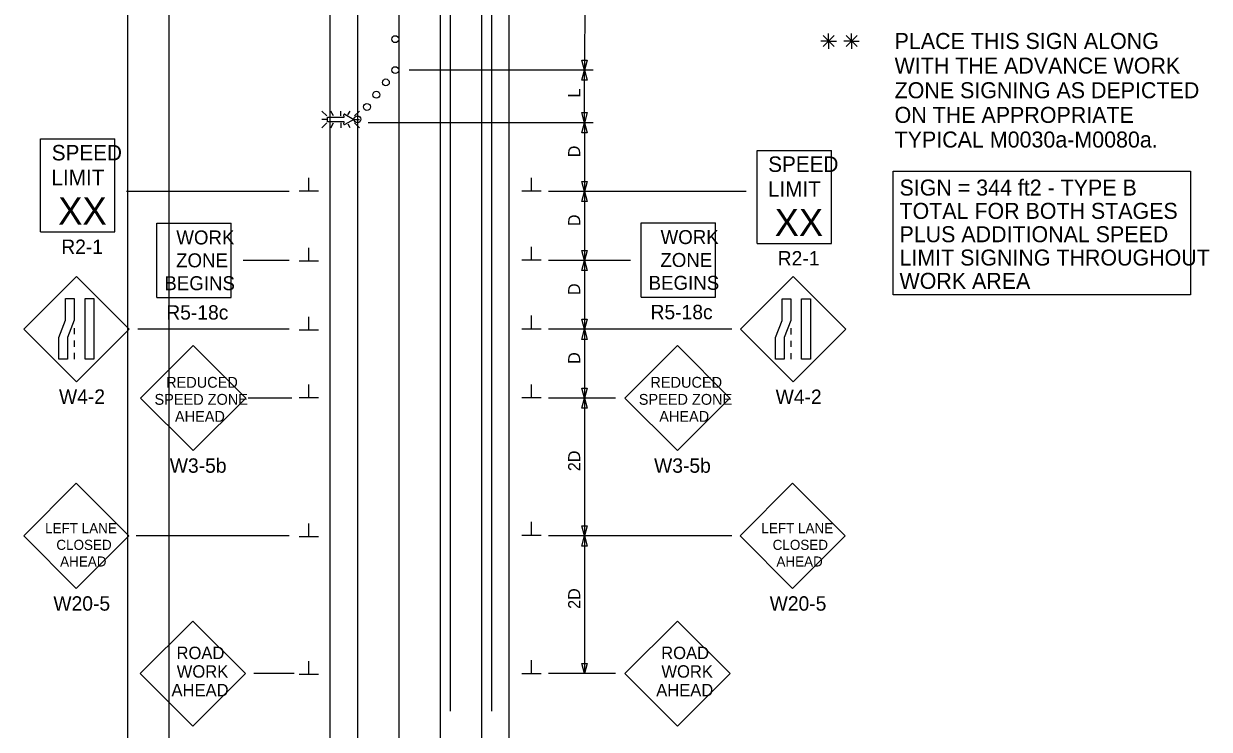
# Model space of a CAD drawing. Extents: x 16576 to 19504, y 5728 to 6974.
# Drawn here: x 16733 to 17422, y 6145 to 6555 of the extents above; entities that cross this region are included whole.
import ezdxf

# ---------------------------------------------------------------- set-up
doc = ezdxf.new("R2010")
doc.units = 0
for name, color, linetype in [('ALI_LEGAL_EX', 7, 'Continuous'), ('PAVT_EDGE_EX', 7, 'Continuous'), ('TRAFFIC_SIGNS_PR', 7, 'Continuous'), ('TYPICAL_TEXT_DIMEN_EX', 7, 'Continuous'), ('TYPICAL_TEXT_DIMEN_PR', 7, 'Continuous')]:
    doc.layers.add(name, color=color, linetype=linetype)

msp = doc.modelspace()

# ---------------------------------------------------------------- linework, layer by layer
at = {"layer": 'ALI_LEGAL_EX'}
for p, q in [((16980.68, 6974.12), (16980.68, 6155.98)), ((17004.68, 6974.12), (17004.68, 6155.98)), ((16950.77, 6911.88), (16950.77, 6082.69)), ((16974.77, 6911.88), (16974.77, 6082.69)), ((16793.2, 6891.57), (16793.2, 6027.66)), ((16817.2, 6891.57), (16817.2, 6027.66))]:
    msp.add_line(p, q, dxfattribs=at)
for points in [[(16950.77, 6511.88), (16950.77, 6486.88)], [(16974.77, 6511.88), (16974.77, 6486.88)], [(16950.77, 6411.88), (16950.77, 6386.88)], [(16974.77, 6411.88), (16974.77, 6386.88)], [(16950.77, 6311.88), (16950.77, 6286.88)], [(16974.77, 6311.88), (16974.77, 6286.88)], [(16950.77, 6211.88), (16950.77, 6186.88)], [(16974.77, 6211.88), (16974.77, 6186.88)]]:
    msp.add_lwpolyline(points, dxfattribs=at)
at = {"layer": 'PAVT_EDGE_EX'}
for p, q in [((16910.77, 6923.28), (16910.77, 5986.88)), ((16926.77, 6923.28), (16926.77, 5986.88)), ((16998.77, 6923.28), (16998.77, 5986.88)), ((17014.77, 6923.28), (17014.77, 5986.88))]:
    msp.add_line(p, q, dxfattribs=at)
at = {"layer": 'TRAFFIC_SIGNS_PR'}
for p, q in [((16908.93, 6501.61), (16906.11, 6504.43)), ((16908.93, 6499.58), (16906.11, 6499.58)), ((16912.88, 6501.61), (16911.26, 6504.43)), ((16917.02, 6501.61), (16917.02, 6504.43)), ((16921.2, 6502.25), (16922.46, 6504.43)), ((16927.92, 6504.43), (16925.1, 6501.61)), ((16925.1, 6499.58), (16927.92, 6499.58)), ((16908.93, 6497.55), (16906.11, 6494.73)), ((16911.23, 6494.73), (16912.86, 6497.55)), ((16917.02, 6497.55), (16917.02, 6494.73)), ((16922.49, 6494.73), (16921.28, 6496.82)), ((16927.92, 6494.73), (16925.1, 6497.55)), ((16742.6, 6488.3), (16785.8, 6488.3)), ((16742.6, 6434.3), (16742.6, 6488.3)), ((16785.8, 6434.3), (16785.8, 6488.3)), ((17159, 6481.61), (17202.2, 6481.61)), ((17159, 6427.61), (17159, 6481.61)), ((17202.2, 6427.61), (17202.2, 6481.61)), ((16810.23, 6396.18), (16810.23, 6439.38)), ((16810.23, 6439.38), (16853.43, 6439.38)), ((16853.43, 6396.18), (16853.43, 6439.38)), ((17091.69, 6396.39), (17091.69, 6439.59)), ((17091.69, 6439.59), (17134.89, 6439.59)), ((17134.89, 6396.39), (17134.89, 6439.59)), ((16742.6, 6434.3), (16785.8, 6434.3)), ((17159, 6427.61), (17202.2, 6427.61)), ((16763.47, 6408.35), (16732.92, 6377.81)), ((16794.02, 6377.81), (16763.47, 6408.35)), ((17179.99, 6408.26), (17149.44, 6377.72)), ((17210.53, 6377.72), (17179.99, 6408.26)), ((16810.23, 6396.18), (16853.43, 6396.18)), ((17091.69, 6396.39), (17134.89, 6396.39)), ((16732.92, 6377.81), (16763.47, 6347.26)), ((16762.07, 6378.36), (16762.07, 6374.76)), ((16763.47, 6347.26), (16794.02, 6377.81)), ((17149.44, 6377.72), (17179.99, 6347.17)), ((17178.58, 6378.27), (17178.58, 6374.67)), ((17179.99, 6347.17), (17210.53, 6377.72)), ((16762.07, 6371.16), (16762.07, 6367.56)), ((16831.25, 6368.32), (16800.71, 6337.77)), ((16861.8, 6337.77), (16831.25, 6368.32)), ((17112.72, 6368.32), (17082.17, 6337.77)), ((17143.26, 6337.77), (17112.72, 6368.32)), ((17178.58, 6371.07), (17178.58, 6367.47)), ((16762.07, 6363.96), (16762.07, 6360.36)), ((17178.58, 6363.87), (17178.58, 6360.27)), ((16800.71, 6337.77), (16831.25, 6307.22)), ((16831.25, 6307.22), (16861.8, 6337.77)), ((17082.17, 6337.77), (17112.72, 6307.22)), ((17112.72, 6307.22), (17143.26, 6337.77)), ((16763.33, 6288.22), (16732.79, 6257.68)), ((16793.88, 6257.68), (16763.33, 6288.22)), ((17179.64, 6288.22), (17149.09, 6257.68)), ((17210.19, 6257.68), (17179.64, 6288.22)), ((16732.79, 6257.68), (16763.33, 6227.13)), ((16763.33, 6227.13), (16793.88, 6257.68)), ((17149.09, 6257.68), (17179.64, 6227.13)), ((17179.64, 6227.13), (17210.19, 6257.68)), ((16831.1, 6208.22), (16800.56, 6177.68)), ((16861.65, 6177.68), (16831.1, 6208.22)), ((17112.8, 6208.22), (17082.25, 6177.68)), ((17143.34, 6177.68), (17112.8, 6208.22)), ((16800.56, 6177.68), (16831.1, 6147.13)), ((16831.1, 6147.13), (16861.65, 6177.68)), ((17082.25, 6177.68), (17112.8, 6147.13)), ((17112.8, 6147.13), (17143.34, 6177.68))]:
    msp.add_line(p, q, dxfattribs=at)
for points in [[(16918.85, 6496.9), (16919.07, 6498.19), (16909.35, 6498.19), (16909.35, 6500.94), (16919.07, 6500.94), (16918.84, 6502.24)], [(16919.35, 6502.6), (16924.65, 6499.58), (16919.34, 6496.54)]]:
    msp.add_lwpolyline(points, dxfattribs=at)
for points in [[(16762.07, 6395.51), (16762.07, 6382.93), (16758.3, 6372.94), (16758.3, 6360.36), (16753.25, 6360.36), (16753.25, 6372.94), (16757.01, 6382.93), (16757.01, 6395.51)], [(16773.47, 6395.51), (16773.47, 6360.36), (16768.41, 6360.36), (16768.41, 6395.51)], [(17178.58, 6395.42), (17178.58, 6382.84), (17174.82, 6372.85), (17174.82, 6360.27), (17169.77, 6360.27), (17169.77, 6372.85), (17173.53, 6382.84), (17173.53, 6395.42)], [(17189.99, 6395.42), (17189.99, 6360.27), (17184.93, 6360.27), (17184.93, 6395.42)]]:
    msp.add_lwpolyline(points, close=True, dxfattribs=at)
for centre in [(16948.76, 6546.19), (16948.76, 6528.19), (16943.26, 6521.06), (16937.77, 6513.93), (16932.27, 6506.8), (16926.77, 6499.68)]:
    msp.add_circle(centre, 2, dxfattribs=at)
for centre, start, end in [((16919.18, 6502.3), 61.10835, 189.26922), ((16919.18, 6496.84), 170.04067, 298.51671)]:
    msp.add_arc(centre, 0.341, start, end, dxfattribs=at)
at = {"layer": 'TYPICAL_TEXT_DIMEN_EX'}
for p, q in [((17197.42, 6548.24), (17203.8, 6541.86)), ((17203.8, 6548.24), (17197.42, 6541.86)), ((17200.61, 6545.05), (17200.61, 6549.5)), ((17217.12, 6548.24), (17210.74, 6541.86)), ((17210.75, 6548.24), (17217.12, 6541.86)), ((17213.93, 6545.05), (17213.93, 6549.5)), ((17200.61, 6545.05), (17196.08, 6545.05)), ((17200.61, 6545.05), (17203.8, 6545.05)), ((17200.61, 6545.05), (17205.09, 6545.05)), ((17200.61, 6545.05), (17200.61, 6540.55)), ((17213.93, 6545.05), (17209.4, 6545.05)), ((17213.93, 6545.05), (17217.12, 6545.05)), ((17213.93, 6545.05), (17218.41, 6545.05)), ((17213.93, 6545.05), (17213.93, 6540.55))]:
    msp.add_line(p, q, dxfattribs=at)
msp.add_lwpolyline([(17238.08, 6469.56), (17410.91, 6469.56), (17410.91, 6397.64), (17238.08, 6397.64)], close=True, dxfattribs=at)
at = {"layer": 'TYPICAL_TEXT_DIMEN_PR'}
for p, q in [((17058.86, 6620.24), (17058.77, 6528.19)), ((17058.77, 6528.19), (17057.2, 6534.05)), ((17057.2, 6534.05), (17058.77, 6534.05)), ((17058.77, 6534.05), (17060.34, 6534.05)), ((17060.34, 6534.05), (17058.77, 6528.19)), ((17063.77, 6528.19), (16956.85, 6528.19)), ((17057.2, 6522.33), (17058.77, 6528.19)), ((17058.77, 6497.68), (17058.77, 6528.19)), ((17058.77, 6528.19), (17060.34, 6522.33)), ((17058.77, 6522.33), (17057.2, 6522.33)), ((17060.34, 6522.33), (17058.77, 6522.33)), ((17058.77, 6497.68), (17057.2, 6503.54)), ((17057.2, 6503.54), (17058.77, 6503.54)), ((17058.77, 6503.54), (17060.34, 6503.54)), ((17060.34, 6503.54), (17058.77, 6497.68)), ((17063.77, 6497.68), (16933.03, 6497.68)), ((17057.2, 6491.82), (17058.77, 6497.68)), ((17058.77, 6491.82), (17057.2, 6491.82)), ((17058.77, 6497.68), (17058.77, 6457.68)), ((17058.77, 6497.68), (17060.34, 6491.82)), ((17060.34, 6491.82), (17058.77, 6491.82)), ((16898.42, 6457.85), (16898.42, 6465.63)), ((17027.9, 6457.85), (17027.9, 6465.63)), ((17058.77, 6457.68), (17057.2, 6463.54)), ((17057.2, 6463.54), (17058.77, 6463.54)), ((17058.77, 6463.54), (17060.34, 6463.54)), ((17060.34, 6463.54), (17058.77, 6457.68)), ((16887.06, 6457.68), (16792.44, 6457.68)), ((16904.05, 6457.85), (16892.8, 6457.85)), ((17033.52, 6457.85), (17022.27, 6457.85)), ((17152.74, 6457.68), (17037.77, 6457.68)), ((17057.2, 6451.82), (17058.77, 6457.68)), ((17058.77, 6457.68), (17058.77, 6417.68)), ((17058.77, 6457.68), (17060.34, 6451.82)), ((17058.77, 6451.82), (17057.2, 6451.82)), ((17060.34, 6451.82), (17058.77, 6451.82)), ((16898.42, 6417.16), (16898.42, 6424.94)), ((17027.9, 6417.85), (17027.9, 6425.63)), ((17058.77, 6417.68), (17057.2, 6423.54)), ((17057.2, 6423.54), (17058.77, 6423.54)), ((17058.77, 6423.54), (17060.34, 6423.54)), ((17060.34, 6423.54), (17058.77, 6417.68)), ((16887.06, 6417.68), (16860.26, 6417.68)), ((16904.05, 6417.16), (16892.8, 6417.16)), ((17033.52, 6417.85), (17022.27, 6417.85)), ((17085.38, 6417.68), (17037.77, 6417.68)), ((17057.2, 6411.82), (17058.77, 6417.68)), ((17058.77, 6417.68), (17058.77, 6377.68)), ((17058.77, 6417.68), (17060.34, 6411.82)), ((17058.77, 6411.82), (17057.2, 6411.82)), ((17060.34, 6411.82), (17058.77, 6411.82)), ((16898.42, 6377.16), (16898.42, 6384.94)), ((17027.9, 6377.85), (17027.9, 6385.63)), ((17058.77, 6377.68), (17057.2, 6383.54)), ((17057.2, 6383.54), (17058.77, 6383.54)), ((17058.77, 6383.54), (17060.34, 6383.54)), ((17060.34, 6383.54), (17058.77, 6377.68)), ((16887.06, 6377.68), (16799.05, 6377.68)), ((16904.05, 6377.16), (16892.8, 6377.16)), ((17033.52, 6377.85), (17022.27, 6377.85)), ((17144.32, 6377.68), (17037.77, 6377.68)), ((17057.2, 6371.82), (17058.77, 6377.68)), ((17058.77, 6377.68), (17058.77, 6337.68)), ((17058.77, 6377.68), (17060.34, 6371.82)), ((17058.77, 6371.82), (17057.2, 6371.82)), ((17060.34, 6371.82), (17058.77, 6371.82)), ((16898.42, 6337.84), (16898.42, 6345.62)), ((17027.9, 6337.85), (17027.9, 6345.63)), ((17058.77, 6337.68), (17057.2, 6343.54)), ((17057.2, 6343.54), (17058.77, 6343.54)), ((17058.77, 6343.54), (17060.34, 6343.54)), ((17060.34, 6343.54), (17058.77, 6337.68)), ((16888.63, 6337.68), (16863.25, 6337.68)), ((16904.05, 6337.84), (16892.8, 6337.84)), ((17033.52, 6337.85), (17022.27, 6337.85)), ((17076.69, 6337.68), (17037.77, 6337.68)), ((17057.2, 6331.82), (17058.77, 6337.68)), ((17058.77, 6337.68), (17058.77, 6257.68)), ((17058.77, 6337.68), (17060.34, 6331.82)), ((17058.77, 6331.82), (17057.2, 6331.82)), ((17060.34, 6331.82), (17058.77, 6331.82)), ((16898.42, 6257.16), (16898.42, 6264.94)), ((17027.9, 6258), (17027.9, 6265.78)), ((17058.77, 6257.68), (17057.2, 6263.54)), ((17057.2, 6263.54), (17058.77, 6263.54)), ((17058.77, 6263.54), (17060.34, 6263.54)), ((17060.34, 6263.54), (17058.77, 6257.68)), ((16887.06, 6257.68), (16798.19, 6257.68)), ((16904.05, 6257.16), (16892.8, 6257.16)), ((17033.52, 6258), (17022.27, 6258)), ((17144.32, 6257.68), (17037.77, 6257.68)), ((17057.2, 6251.82), (17058.77, 6257.68)), ((17058.77, 6257.68), (17058.77, 6177.68)), ((17058.77, 6257.68), (17060.34, 6251.82)), ((17058.77, 6251.82), (17057.2, 6251.82)), ((17060.34, 6251.82), (17058.77, 6251.82)), ((16898.42, 6177.16), (16898.42, 6184.94)), ((17027.9, 6177.67), (17027.9, 6185.46)), ((17058.77, 6177.68), (17057.2, 6183.54)), ((17057.2, 6183.54), (17058.77, 6183.54)), ((17058.77, 6183.54), (17060.34, 6183.54)), ((17060.34, 6183.54), (17058.77, 6177.68)), ((16889.91, 6177.68), (16866.6, 6177.68)), ((16904.05, 6177.16), (16892.8, 6177.16)), ((17033.52, 6177.67), (17022.27, 6177.67)), ((17076.69, 6177.68), (17037.77, 6177.68))]:
    msp.add_line(p, q, dxfattribs=at)

# ---------------------------------------------------------------- texts
at = {"layer": 'TRAFFIC_SIGNS_PR'}
for s, height, p in [('SPEED', 9, (16749.08, 6475.76)), ('SPEED', 9, (17165.48, 6469.08)), ('LIMIT', 9, (16748.9, 6461.36)), ('LIMIT', 9, (17165.3, 6454.68)), ('XX', 15.785, (16752.85, 6438.52)), ('XX', 15.785, (17169.25, 6431.84)), ('R2-1', 8.37, (16754.61, 6421.43)), ('WORK', 8.119, (16821.48, 6426.97)), ('WORK', 8.119, (17102.94, 6427.18)), ('ZONE', 8.119, (17102.81, 6413.89)), ('R2-1', 8.37, (17171.01, 6414.74)), ('ZONE', 8.119, (16821.35, 6413.68)), ('BEGINS', 8.119, (16814.52, 6400.4)), ('BEGINS', 8.119, (17095.98, 6400.61)), ('R5-18c', 8.37, (16815.65, 6383.31)), ('R5-18c', 8.37, (17097.11, 6383.52)), ('REDUCED', 6.3, (16815.57, 6343.74)), ('REDUCED', 6.3, (17097.03, 6343.74)), ('W4-2', 8.37, (16753.3, 6334.39)), ('SPEED ZONE', 6.3, (16808.81, 6333.84)), ('SPEED ZONE', 6.3, (17090.27, 6333.84)), ('W4-2', 8.37, (17169.81, 6334.3)), ('AHEAD', 6.3, (16820.69, 6323.94)), ('AHEAD', 6.3, (17102.15, 6323.94)), ('W3-5b', 8.37, (16817.7, 6294.35)), ('W3-5b', 8.37, (17099.16, 6294.35)), ('LEFT LANE', 5.85, (16745.2, 6259.25)), ('LEFT LANE', 5.85, (17161.51, 6259.25)), ('CLOSED', 5.85, (16751.76, 6249.57)), ('CLOSED', 5.85, (17168.07, 6249.57)), ('AHEAD', 5.85, (16753.95, 6239.9)), ('AHEAD', 5.85, (17170.26, 6239.9)), ('W20-5', 8.37, (16750.03, 6214.26)), ('W20-5', 8.37, (17166.33, 6214.26)), ('ROAD', 7.2, (16821.59, 6186.15)), ('ROAD', 7.2, (17103.28, 6186.15)), ('WORK', 7.2, (16821.71, 6175.35)), ('WORK', 7.2, (17103.4, 6175.35)), ('AHEAD', 7.2, (16818.68, 6164.55)), ('AHEAD', 7.2, (17100.38, 6164.55))]:
    msp.add_text(s, height=height, dxfattribs=at).set_placement(p)
at = {"layer": 'TYPICAL_TEXT_DIMEN_EX'}
for s, height, p in [('PLACE THIS SIGN ALONG', 9.31, (17238.94, 6540.49)), ('WITH THE ADVANCE WORK', 9.31, (17238.94, 6526.18)), ('ZONE SIGNING AS DEPICTED', 9.31, (17238.94, 6511.87)), ('ON THE APPROPRIATE', 9.31, (17238.94, 6497.56)), ('TYPICAL M0030a-M0080a.', 9.31, (17238.94, 6483.25)), ('SIGN = 344 ft2 - TYPE B', 9.3, (17241.8, 6455.36)), ('TOTAL FOR BOTH STAGES', 9.3, (17241.8, 6441.81)), ('PLUS ADDITIONAL SPEED', 9.3, (17241.8, 6428.26)), ('LIMIT SIGNING THROUGHOUT', 9.3, (17241.8, 6414.71)), ('WORK AREA', 9.3, (17241.8, 6401.16))]:
    msp.add_text(s, height=height, dxfattribs=at).set_placement(p)
at = {"layer": 'TYPICAL_TEXT_DIMEN_PR'}
for s, p in [('L', (17056.21, 6512.29)), ('D', (17056.21, 6477.59)), ('D', (17056.21, 6437.59)), ('D', (17056.21, 6397.59)), ('D', (17056.21, 6357.59)), ('2D', (17056.21, 6295.29)), ('2D', (17056.21, 6215.29))]:
    msp.add_text(s, height=7, rotation=90, dxfattribs=at).set_placement(p)

doc.saveas('drawing.dxf')
